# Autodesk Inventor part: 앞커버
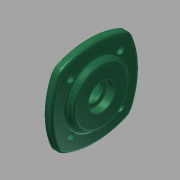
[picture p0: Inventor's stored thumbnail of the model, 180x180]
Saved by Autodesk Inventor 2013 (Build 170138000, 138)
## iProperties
Created: 2015-11
Part Number: 앞커버
Material: 일반
Document SubType Name: Modeling
Designer: mduedu
Density: 1 g/cm^3
Mass: 112.858 g
Surface Area: 251.177 cm^2
Volume: 112.858 cm^3
Author: mduedu
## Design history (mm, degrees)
sketch "스케치1"
  geometry: L1 (50, 50)-(-50, 50); L2 (-50, 50)-(-50, -50); L3 (-50, -50)-(50, -50); L4 (50, -50)-(50, 50); L5 (0, 50)-(0, -50); L6 (50, 0)-(-50, 0); A1 r 90 centre (-40, 0) between (40.415, -40.415) and (40.415, 40.415); A2 r 90 centre (40, 0) between (-40.415, 40.415) and (-40.415, -40.415); A3 r 90 centre (0, -40) between (40.415, 40.415) and (-40.415, 40.415); A4 r 90 centre (0, 40) between (-40.415, -40.415) and (40.415, -40.415); 2 further points
  constraints: 12 end point, 8 point on circle, 5 midpoint, 4 centre point, 2 horizontal alignment, 2 parallel, 2 perpendicular, 2 symmetric about line, 2 tangent, 2 vertical alignment, 1 equal radius, 1 horizontal, 2 other
  dimensions: "d0" = 100 distance of L3.end L1.start; "d2" = 90 radius of A1
extrude "돌출1" new body sketch "스케치1" distance "d3" = 8; taper "d4" = 0 deg
sketch "스케치2"
  geometry: C1 r 35 at (0, 0); 1 further point
  constraints: 1 centre point, 1 coincident
  dimensions: "d5" = 70 diameter of C1
extrude "돌출2" join sketch "스케치2" distance "d6" = 7; taper "d7" = -30 deg
sketch "스케치3"
  geometry: L1 (0, 0)-(0, 40); L2 (0, 0)-(-28.284, 28.284); A1 r 40 centre (0, 0) between (0, 40) and (-28.284, 28.284); 2 further points
  constraints: 4 end point, 2 coincident, 2 point on circle, 1 centre point, 1 vertical
  dimensions: "d8" = 80 diameter of A1; "d9" = 45 deg angle of L1 L2
hole "구멍1" sketch "스케치3" at (-28.284, 28.284) diameter "d11" = 4.5; stored, may be unused: countersink angle "d15" = 90 deg, drill point angle "d17" = 118 deg; dims "d12" = 6, "d13" = 8, "d14" = 4.4, "d16" = 8
sketch "스케치4"
  geometry: C1 r 35 at (0, 0); 1 further point
  constraints: 1 centre point, 1 coincident
  dimensions: "d21" = 70 diameter of C1
extrude "돌출3" join sketch "스케치4" distance "d23" = 12; taper "d24" = 0 deg
hole "구멍2" diameter "d27" = 30; stored, may be unused: countersink angle "d31" = 90 deg, drill point angle "d33" = 0 deg; dims "d25" = 10, "d26" = 10, "d28" = 6, "d29" = 40, "d30" = 12, "d32" = 15
fillet "모깎기2" dims "d35" = 15
fillet "모깎기3" dims "d36" = 3
fillet "모깎기4" dims "d37" = 3
fillet "모깎기5" dims "d38" = 0.3
chamfer "모따기1" distance "d39" = 1; stored, may be unused: second distance "d40" = 2, angle "d41" = 45 deg
hole "구멍3" diameter "d44" = 20; stored, may be unused: countersink angle "d48" = 90 deg, drill point angle "d50" = 118 deg; dims "d45" = 6, "d46" = 30, "d47" = 8.7, "d49" = 8, "d55" = 10, "d56" = 10
fillet "모깎기6" dims "d51" = 0.3
chamfer "모따기2" distance "d52" = 0.7; stored, may be unused: second distance "d53" = 2, angle "d54" = 30 deg
node "솔리드1"
pattern_circular "원형 패턴1" dims angle "d19" = 360 deg
